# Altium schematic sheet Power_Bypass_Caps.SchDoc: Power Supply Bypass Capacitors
size A4; DocumentNumber: 10; SheetNumber: 10; SheetTotal: 12
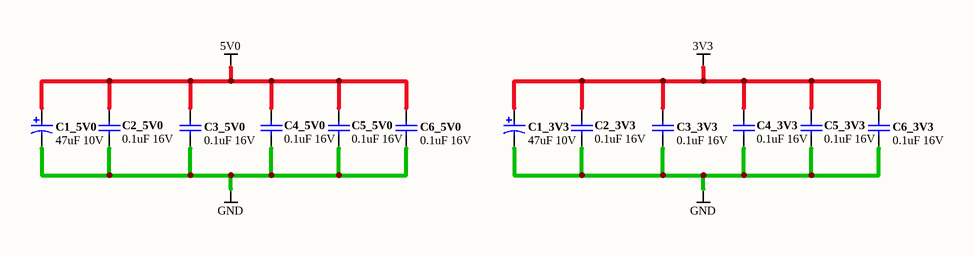
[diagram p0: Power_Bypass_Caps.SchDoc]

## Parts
C1_3V3  47uF 10V  [CAPC3528-STAR]
C1_5V0  47uF 10V  [CAPC3528-STAR]
C2_3V3  0.1uF 16V  [CAPC1005-STAR]
C2_5V0  0.1uF 16V  [CAPC1005-STAR]
C3_3V3  0.1uF 16V  [CAPC1005-STAR]
C3_5V0  0.1uF 16V  [CAPC1005-STAR]
C4_3V3  0.1uF 16V  [CAPC1005-STAR]
C4_5V0  0.1uF 16V  [CAPC1005-STAR]
C5_3V3  0.1uF 16V  [CAPC1005-STAR]
C5_5V0  0.1uF 16V  [CAPC1005-STAR]
C6_3V3  0.1uF 16V  [CAPC1005-STAR]
C6_5V0  0.1uF 16V  [CAPC1005-STAR]

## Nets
3V3: C1_3V3.1 C2_3V3.2 C3_3V3.1 C4_3V3.2 C5_3V3.2 C6_3V3.1
5V0: C1_5V0.1 C2_5V0.2 C3_5V0.1 C4_5V0.2 C5_5V0.2 C6_5V0.1
GND: C1_3V3.2 C1_5V0.2 C2_3V3.1 C2_5V0.1 C3_3V3.2 C3_5V0.2 C4_3V3.1 C4_5V0.1 C5_3V3.1 C5_5V0.1 C6_3V3.2 C6_5V0.2

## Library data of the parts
C1_3V3 C1_5V0 = D-101-0001: Capacitor, Tantalum, 47uF 20% 10V MCCT-B (3528-12); Polarity: Polarized
C2_3V3 C2_5V0 C3_3V3 C3_5V0 C4_3V3 C4_5V0 C5_3V3 C5_5V0 C6_3V3 C6_5V0 = D-101-0080: Capacitor, Ceramic, 0.1uF 10% 16V 0402 (1005) X7R; Polarity: Non-Polarized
